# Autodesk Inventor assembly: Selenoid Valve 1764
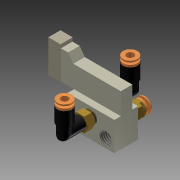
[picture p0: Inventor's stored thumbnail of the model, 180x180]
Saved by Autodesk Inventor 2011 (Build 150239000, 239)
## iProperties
Created: 2010-02
Part Number: Selenoid Valve 1764
Document SubType Name: Assembly
Designer: jgehrig
Author: jgehrig
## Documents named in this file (5)
- R:\CAD Archives\Pneumatics\Seloniod 1764\Selenoid Valve 1764.iam
- R:\CAD Archives\Pneumatics\Seloniod 1764\Selenoid Base 1764.ipt
- R:\CAD Archives\Pneumatics\Seloniod 1764\Selenoid Part 1764.ipt
- R:\CAD Archives\Pneumatics\Seloniod 1764\Pneumatic Screw 1764\Pneumatic Screw 1764.iam
- R:\CAD Archives\Pneumatics\Pneumatics Bend Piece 1764\Pneumatic Bend Piece 1764.iam
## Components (5 placed, 4 different names)
1. Selenoid Base 1764:1 — Flush:1, Mate:1, Flush:2, Insert:3, Insert:4, Insert:5
2. Selenoid Part 1764:1 — Flush:1, Mate:1, Flush:2, Angle:4, Angle:5
3. Pneumatic Screw 1764:1 [sub-assembly] — Insert:3
4. Pneumatic Bend Piece 1764:1 [sub-assembly] — Insert:5, Angle:4
5. Pneumatic Bend Piece 1764:2 [sub-assembly] — Insert:4, Angle:5
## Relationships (8: Insert 3, Flush 2, Angle 2, Mate 1)
- Flush:1: Selenoid Base 1764:1 ↔ Selenoid Part 1764:1
- Mate:1: Selenoid Base 1764:1 ↔ Selenoid Part 1764:1
- Flush:2: Selenoid Base 1764:1 ↔ Selenoid Part 1764:1
- Insert:3: Selenoid Base 1764:1 ↔ Pneumatic Screw 1764:1
- Insert:4: Selenoid Base 1764:1 ↔ Pneumatic Bend Piece 1764:2
- Insert:5: Selenoid Base 1764:1 ↔ Pneumatic Bend Piece 1764:1
- Angle:4: Selenoid Part 1764:1 ↔ Pneumatic Bend Piece 1764:1
- Angle:5: Selenoid Part 1764:1 ↔ Pneumatic Bend Piece 1764:2
